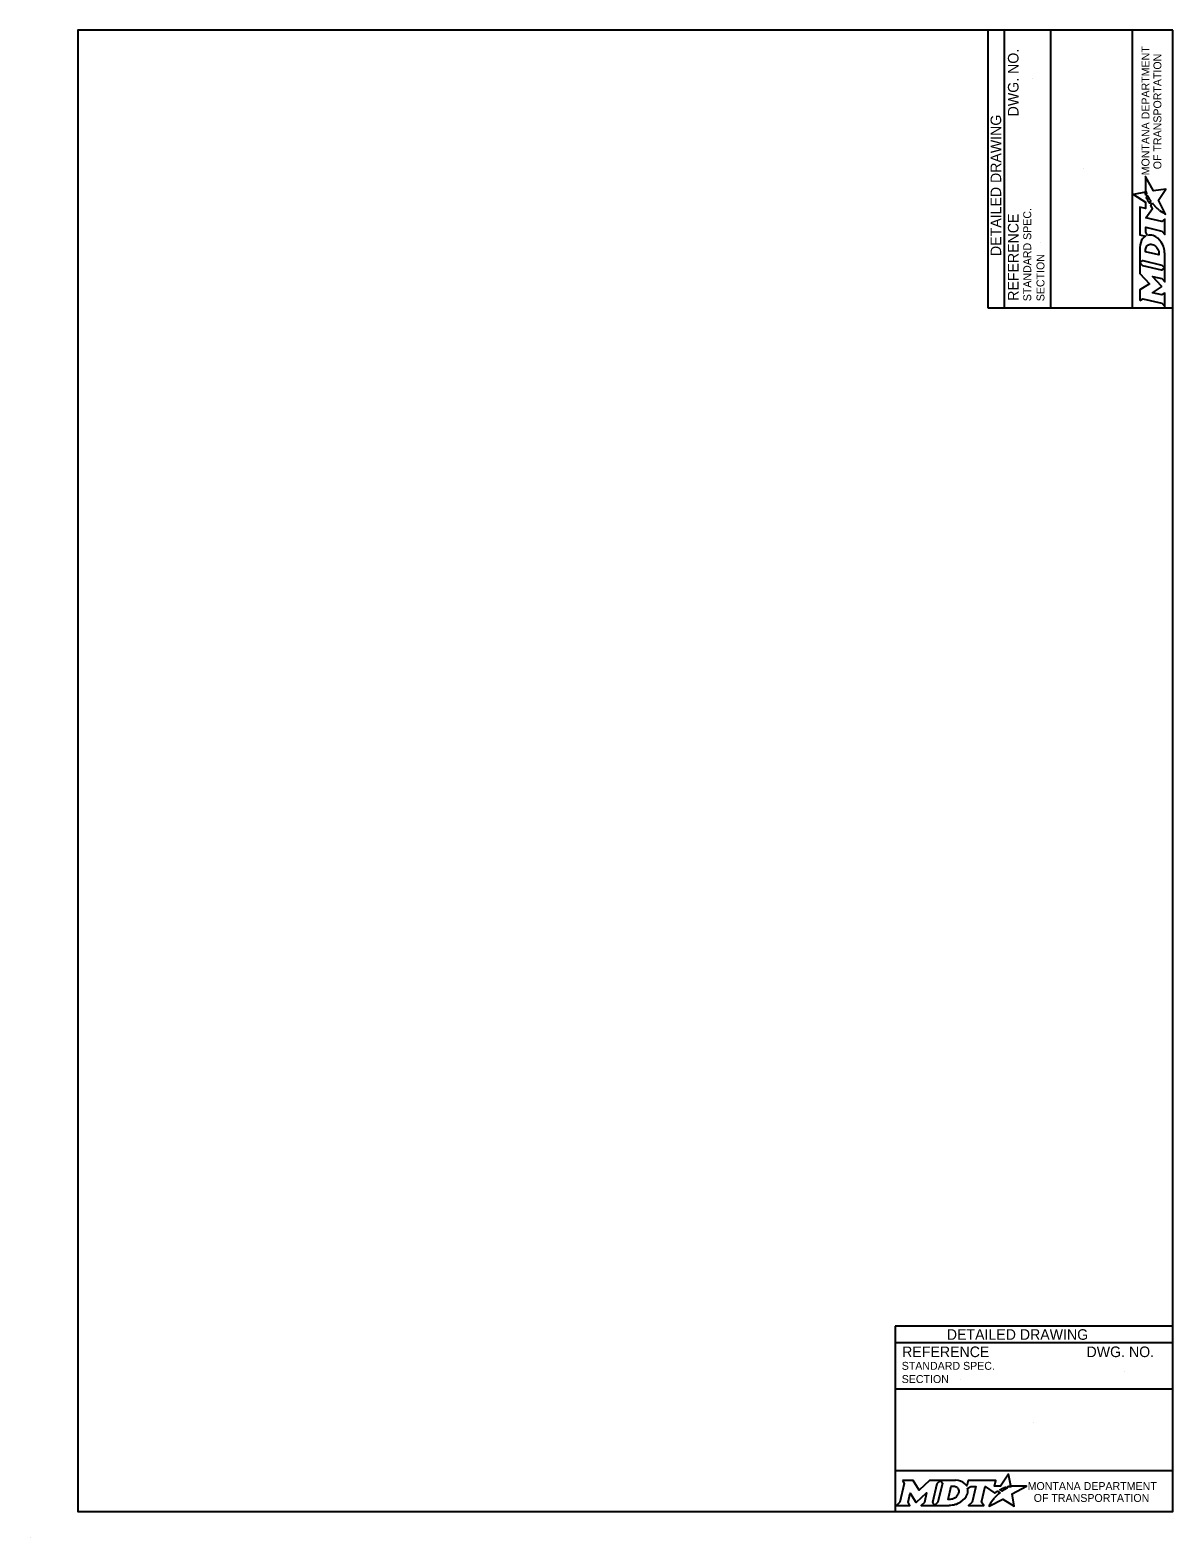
# Model space of a CAD drawing. Extents: x 49991 to 50288, y 49919 to 50011.
# Drawn here: x 49999.98 to 50008.61, y 49999.86 to 50011.26 of the extents above; entities that cross this region are included whole.
import ezdxf

# ---------------------------------------------------------------- set-up
doc = ezdxf.new("R2010")
doc.units = 0
for name, color, linetype in [('Level 1', 7, 'Continuous'), ('Level 2', 7, 'Continuous'), ('Level 3', 7, 'Continuous')]:
    doc.layers.add(name, color=color, linetype=linetype)

msp = doc.modelspace()

# ---------------------------------------------------------------- linework, layer by layer
at = {"layer": 'Level 1'}
msp.add_line((49999.977, 49999.862), (49999.977, 49999.862), dxfattribs=at)
msp.add_line((49999.977, 49999.862), (49999.977, 49999.862), dxfattribs=at)
msp.add_lwpolyline([(50008.615, 50011.263), (50000.336, 50011.263), (50000.336, 50000.062), (50008.615, 50000.062)], close=True, dxfattribs=at)
msp.add_lwpolyline([(50008.615, 50011.263), (50000.336, 50011.263), (50000.336, 50000.062), (50008.615, 50000.062)], close=True, dxfattribs=at)
at = {"layer": 'Level 2'}
for p, q in [((50008.615, 50001.462), (50006.515, 50001.462)), ((50006.515, 50001.462), (50006.515, 50000.062)), ((50008.615, 50001.462), (50006.515, 50001.462)), ((50006.515, 50001.462), (50006.515, 50000.062)), ((50008.615, 50001.337), (50006.515, 50001.337)), ((50008.615, 50001.337), (50006.515, 50001.337)), ((50007.009, 50001.063), (50007.009, 50001.063)), ((50007.009, 50001.063), (50007.009, 50001.063)), ((50008.251, 50001.122), (50008.251, 50001.122)), ((50008.251, 50001.122), (50008.251, 50001.122)), ((50008.615, 50000.987), (50006.515, 50000.987)), ((50008.615, 50000.987), (50006.515, 50000.987)), ((50007.565, 50000.738), (50007.565, 50000.738)), ((50007.565, 50000.738), (50007.565, 50000.738)), ((50008.615, 50000.369), (50006.515, 50000.369)), ((50008.615, 50000.369), (50006.515, 50000.369))]:
    msp.add_line(p, q, dxfattribs=at)
for points in [[(50007.377, 50000.245), (50007.367, 50000.25), (50007.378, 50000.253), (50007.39, 50000.255), (50007.373, 50000.345), (50007.313, 50000.254), (50007.266, 50000.253), (50007.276, 50000.297), (50007.067, 50000.297), (50007.057, 50000.255), (50007.051, 50000.263)], [(50007.377, 50000.245), (50007.367, 50000.25), (50007.378, 50000.253), (50007.39, 50000.255), (50007.373, 50000.345), (50007.313, 50000.254), (50007.266, 50000.253), (50007.276, 50000.297), (50007.067, 50000.297), (50007.057, 50000.255), (50007.051, 50000.263)], [(50006.57, 50000.297), (50006.584, 50000.274), (50006.551, 50000.131), (50006.525, 50000.108), (50006.627, 50000.108), (50006.613, 50000.131), (50006.629, 50000.201), (50006.673, 50000.132), (50006.678, 50000.132), (50006.753, 50000.202), (50006.737, 50000.13), (50006.712, 50000.108), (50006.814, 50000.108), (50006.8, 50000.132), (50006.833, 50000.274)], [(50006.57, 50000.297), (50006.584, 50000.274), (50006.551, 50000.131), (50006.525, 50000.108), (50006.627, 50000.108), (50006.613, 50000.131), (50006.629, 50000.201), (50006.673, 50000.132), (50006.678, 50000.132), (50006.753, 50000.202), (50006.737, 50000.13), (50006.712, 50000.108), (50006.814, 50000.108), (50006.8, 50000.132), (50006.833, 50000.274)], [(50006.833, 50000.274), (50006.859, 50000.297), (50006.776, 50000.297), (50006.697, 50000.224), (50006.652, 50000.297), (50006.57, 50000.297)], [(50006.833, 50000.274), (50006.859, 50000.297), (50006.776, 50000.297), (50006.697, 50000.224), (50006.652, 50000.297), (50006.57, 50000.297)], [(50006.972, 50000.297), (50006.859, 50000.297), (50006.873, 50000.275), (50006.839, 50000.131), (50006.814, 50000.108), (50006.925, 50000.108)], [(50006.972, 50000.297), (50006.859, 50000.297), (50006.873, 50000.275), (50006.839, 50000.131), (50006.814, 50000.108), (50006.925, 50000.108)], [(50006.996, 50000.211), (50006.995, 50000.203), (50006.992, 50000.193), (50006.988, 50000.185), (50006.982, 50000.178), (50006.976, 50000.171), (50006.968, 50000.164), (50006.959, 50000.16), (50006.95, 50000.156), (50006.941, 50000.154), (50006.932, 50000.153), (50006.916, 50000.153), (50006.94, 50000.253), (50006.956, 50000.253), (50006.963, 50000.252), (50006.971, 50000.25), (50006.977, 50000.247), (50006.983, 50000.243), (50006.988, 50000.238), (50006.992, 50000.232), (50006.995, 50000.226), (50006.996, 50000.218), (50006.996, 50000.215), (50006.996, 50000.211)], [(50006.996, 50000.211), (50006.995, 50000.203), (50006.992, 50000.193), (50006.988, 50000.185), (50006.982, 50000.178), (50006.976, 50000.171), (50006.968, 50000.164), (50006.959, 50000.16), (50006.95, 50000.156), (50006.941, 50000.154), (50006.932, 50000.153), (50006.916, 50000.153), (50006.94, 50000.253), (50006.956, 50000.253), (50006.963, 50000.252), (50006.971, 50000.25), (50006.977, 50000.247), (50006.983, 50000.243), (50006.988, 50000.238), (50006.992, 50000.232), (50006.995, 50000.226), (50006.996, 50000.218), (50006.996, 50000.215), (50006.996, 50000.211)], [(50007.064, 50000.238), (50007.088, 50000.251), (50007.125, 50000.251), (50007.097, 50000.131), (50007.069, 50000.108), (50007.185, 50000.108), (50007.168, 50000.131), (50007.196, 50000.251), (50007.268, 50000.2), (50007.289, 50000.215), (50007.309, 50000.204)], [(50007.064, 50000.238), (50007.088, 50000.251), (50007.125, 50000.251), (50007.097, 50000.131), (50007.069, 50000.108), (50007.185, 50000.108), (50007.168, 50000.131), (50007.196, 50000.251), (50007.268, 50000.2), (50007.289, 50000.215), (50007.309, 50000.204)], [(50007.253, 50000.148), (50007.237, 50000.124), (50007.233, 50000.116), (50007.227, 50000.107), (50007.225, 50000.103), (50007.33, 50000.156), (50007.414, 50000.101), (50007.401, 50000.194), (50007.508, 50000.252), (50007.458, 50000.253), (50007.428, 50000.253), (50007.407, 50000.254), (50007.401, 50000.252), (50007.396, 50000.251), (50007.387, 50000.249), (50007.377, 50000.245)], [(50007.253, 50000.148), (50007.237, 50000.124), (50007.233, 50000.116), (50007.227, 50000.107), (50007.225, 50000.103), (50007.33, 50000.156), (50007.414, 50000.101), (50007.401, 50000.194), (50007.508, 50000.252), (50007.458, 50000.253), (50007.428, 50000.253), (50007.407, 50000.254), (50007.401, 50000.252), (50007.396, 50000.251), (50007.387, 50000.249), (50007.377, 50000.245)], [(50007.327, 50000.217), (50007.324, 50000.215), (50007.306, 50000.225), (50007.316, 50000.231), (50007.32, 50000.233), (50007.329, 50000.237), (50007.335, 50000.239), (50007.343, 50000.243), (50007.35, 50000.245), (50007.362, 50000.238), (50007.358, 50000.236), (50007.353, 50000.233), (50007.349, 50000.231), (50007.344, 50000.228), (50007.342, 50000.227), (50007.339, 50000.225), (50007.337, 50000.224), (50007.334, 50000.222), (50007.332, 50000.221), (50007.329, 50000.219), (50007.327, 50000.217)], [(50007.327, 50000.217), (50007.324, 50000.215), (50007.306, 50000.225), (50007.316, 50000.231), (50007.32, 50000.233), (50007.329, 50000.237), (50007.335, 50000.239), (50007.343, 50000.243), (50007.35, 50000.245), (50007.362, 50000.238), (50007.358, 50000.236), (50007.353, 50000.233), (50007.349, 50000.231), (50007.344, 50000.228), (50007.342, 50000.227), (50007.339, 50000.225), (50007.337, 50000.224), (50007.334, 50000.222), (50007.332, 50000.221), (50007.329, 50000.219), (50007.327, 50000.217)], [(50006.97, 50000.116), (50006.979, 50000.118), (50006.992, 50000.124), (50007.012, 50000.135)], [(50006.97, 50000.116), (50006.979, 50000.118), (50006.992, 50000.124), (50007.012, 50000.135)], [(50007.267, 50000.164), (50007.267, 50000.164)], [(50007.267, 50000.164), (50007.267, 50000.164)]]:
    msp.add_lwpolyline(points, dxfattribs=at)
for centre, radius, start, end in [((50006.995, 50000.219), 0.0709, 339.5329, 15.8582), ((50006.995, 50000.219), 0.0709, 339.5329, 15.8582), ((50006.951, 50000.236), 0.118, 300.9103, 339.1383), ((50006.951, 50000.236), 0.118, 300.9103, 339.1383)]:
    msp.add_arc(centre, radius, start, end, dxfattribs=at)
for centre, major_axis, ratio, start_param, end_param in [((50006.97, 50000.25), (0.0834, -0.0037), 0.568097, 0.61298, 1.570796), ((50006.97, 50000.25), (0.0834, -0.0037), 0.568097, 0.61298, 1.570796), ((50007.026, 50000.257), (0.0361, -0.0295), 0.469099, 1.225588, 1.570796), ((50007.026, 50000.257), (0.0361, -0.0295), 0.469099, 1.225588, 1.570796), ((50006.925, 50000.257), (0, 0.148), 0.987302, 3.139398, 3.456847), ((50006.925, 50000.257), (0, 0.148), 0.987302, 3.139398, 3.456847), ((50007.26, 50000.156), (-0.00694, -0.00806), 0.008222, 0, 3.137361), ((50007.26, 50000.156), (-0.00694, -0.00806), 0.008222, 0, 3.137361), ((50007.276, 50000.174), (-0.0098, -0.0102), 0.016458, 3.141593, 6.279097), ((50007.276, 50000.174), (-0.0098, -0.0102), 0.016458, 3.141593, 6.279097), ((50007.297, 50000.194), (-0.0112, -0.0097), 0.021651, 3.157348, 6.283185), ((50007.297, 50000.194), (-0.0112, -0.0097), 0.021651, 3.157348, 6.283185)]:
    msp.add_ellipse(centre, major_axis=major_axis, ratio=ratio, start_param=start_param, end_param=end_param, dxfattribs=at)
at = {"layer": 'Level 3'}
for p, q in [((50007.215, 50011.263), (50007.215, 50009.163)), ((50007.34, 50011.263), (50007.34, 50009.163)), ((50007.69, 50011.263), (50007.69, 50009.163)), ((50008.308, 50011.263), (50008.308, 50009.163)), ((50007.555, 50010.899), (50007.555, 50010.899)), ((50007.939, 50010.213), (50007.939, 50010.213)), ((50007.614, 50009.657), (50007.614, 50009.657)), ((50007.215, 50009.163), (50008.615, 50009.163))]:
    msp.add_line(p, q, dxfattribs=at)
for points in [[(50008.514, 50009.9), (50008.538, 50009.885), (50008.546, 50009.88), (50008.554, 50009.875), (50008.559, 50009.872), (50008.505, 50009.978), (50008.561, 50010.061), (50008.468, 50010.048), (50008.409, 50010.155), (50008.409, 50010.106), (50008.408, 50010.076), (50008.408, 50010.055), (50008.409, 50010.048), (50008.411, 50010.043), (50008.413, 50010.035), (50008.417, 50010.025)], [(50008.417, 50010.025), (50008.411, 50010.014), (50008.409, 50010.026), (50008.407, 50010.038), (50008.316, 50010.02), (50008.408, 50009.961), (50008.408, 50009.914), (50008.364, 50009.924), (50008.364, 50009.715), (50008.407, 50009.705), (50008.398, 50009.699)], [(50008.423, 50009.711), (50008.41, 50009.736), (50008.41, 50009.773), (50008.531, 50009.744), (50008.553, 50009.717), (50008.553, 50009.833), (50008.531, 50009.816), (50008.41, 50009.844), (50008.462, 50009.915), (50008.447, 50009.937), (50008.458, 50009.956)], [(50008.445, 50009.974), (50008.446, 50009.972), (50008.437, 50009.954), (50008.431, 50009.964), (50008.429, 50009.968), (50008.425, 50009.977), (50008.422, 50009.982), (50008.419, 50009.99), (50008.416, 50009.998), (50008.424, 50010.009), (50008.426, 50010.005), (50008.428, 50010.001), (50008.431, 50009.997), (50008.434, 50009.992), (50008.435, 50009.99), (50008.436, 50009.987), (50008.438, 50009.985), (50008.439, 50009.982), (50008.441, 50009.98), (50008.443, 50009.977), (50008.445, 50009.974)], [(50008.498, 50009.914), (50008.498, 50009.914)], [(50008.364, 50009.62), (50008.364, 50009.506), (50008.387, 50009.521), (50008.531, 50009.487), (50008.553, 50009.462), (50008.553, 50009.572)], [(50008.451, 50009.644), (50008.459, 50009.643), (50008.468, 50009.64), (50008.476, 50009.635), (50008.484, 50009.63), (50008.491, 50009.623), (50008.497, 50009.615), (50008.502, 50009.607), (50008.506, 50009.598), (50008.508, 50009.589), (50008.509, 50009.58), (50008.509, 50009.564), (50008.409, 50009.587), (50008.409, 50009.603), (50008.41, 50009.611), (50008.412, 50009.619), (50008.415, 50009.625), (50008.419, 50009.631), (50008.424, 50009.636), (50008.43, 50009.64), (50008.436, 50009.642), (50008.443, 50009.644), (50008.446, 50009.644), (50008.451, 50009.644)], [(50008.546, 50009.618), (50008.543, 50009.626), (50008.538, 50009.639), (50008.527, 50009.66)], [(50008.387, 50009.481), (50008.364, 50009.506), (50008.364, 50009.424), (50008.437, 50009.344), (50008.364, 50009.3), (50008.364, 50009.218)], [(50008.364, 50009.218), (50008.388, 50009.232), (50008.531, 50009.198), (50008.553, 50009.173), (50008.553, 50009.274), (50008.531, 50009.261), (50008.461, 50009.277), (50008.53, 50009.321), (50008.53, 50009.326), (50008.46, 50009.401), (50008.531, 50009.385), (50008.553, 50009.36), (50008.553, 50009.462), (50008.53, 50009.448), (50008.387, 50009.481)]]:
    msp.add_lwpolyline(points, dxfattribs=at)
for centre, radius, start, end in [((50008.443, 50009.643), 0.0709, 69.5329, 105.8582), ((50008.425, 50009.599), 0.118, 30.9103, 69.1383)]:
    msp.add_arc(centre, radius, start, end, dxfattribs=at)
for centre, major_axis, ratio, start_param, end_param in [((50008.468, 50009.945), (0.0097, -0.0112), 0.021651, 3.157348, 6.283185), ((50008.487, 50009.924), (0.0102, -0.0098), 0.016458, 3.141593, 6.279097), ((50008.506, 50009.907), (0.00806, -0.00694), 0.008222, 0, 3.137361), ((50008.412, 50009.618), (0.0037, 0.0834), 0.568097, 0.61298, 1.570796), ((50008.404, 50009.673), (0.0295, 0.0361), 0.469099, 1.225588, 1.570796), ((50008.405, 50009.573), (-0.148, 0), 0.987302, 3.139398, 3.456847)]:
    msp.add_ellipse(centre, major_axis=major_axis, ratio=ratio, start_param=start_param, end_param=end_param, dxfattribs=at)

# ---------------------------------------------------------------- texts
at = {"layer": 'Level 2'}
for s, height, p in [('DETAILED DRAWING', 0.0799, (50006.906, 50001.36)), ('DETAILED DRAWING', 0.0799, (50006.906, 50001.36)), ('REFERENCE', 0.08, (50006.568, 50001.229)), ('REFERENCE', 0.08, (50006.568, 50001.229)), ('DWG. NO.', 0.08, (50007.962, 50001.229)), ('DWG. NO.', 0.08, (50007.962, 50001.229)), ('STANDARD SPEC.', 0.06, (50006.565, 50001.133)), ('STANDARD SPEC.', 0.06, (50006.565, 50001.133)), ('SECTION', 0.06, (50006.565, 50001.033)), ('SECTION', 0.06, (50006.565, 50001.033))]:
    msp.add_text(s, height=height, dxfattribs=at).set_placement(p)
for s, p in [('MONTANA DEPARTMENT', (50007.517, 50000.224)), ('MONTANA DEPARTMENT', (50007.517, 50000.224)), ('OF TRANSPORTATION', (50007.563, 50000.134)), ('OF TRANSPORTATION', (50007.563, 50000.134))]:
    msp.add_text(s, height=0.06, rotation=360, dxfattribs=at).set_placement(p)
at = {"layer": 'Level 3'}
for s, height, p in [('DWG. NO.', 0.08, (50007.448, 50010.611)), ('MONTANA DEPARTMENT', 0.06, (50008.438, 50010.165)), ('OF TRANSPORTATION', 0.06, (50008.528, 50010.211)), ('DETAILED DRAWING', 0.0799, (50007.317, 50009.555)), ('STANDARD SPEC.', 0.06, (50007.544, 50009.213)), ('REFERENCE', 0.08, (50007.448, 50009.216)), ('SECTION', 0.06, (50007.644, 50009.213))]:
    msp.add_text(s, height=height, rotation=90, dxfattribs=at).set_placement(p)

doc.saveas('drawing.dxf')
